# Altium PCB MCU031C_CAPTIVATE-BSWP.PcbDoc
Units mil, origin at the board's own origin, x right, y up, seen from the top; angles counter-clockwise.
Board outline 6000 x 3500 mil, 2 copper layers (Top Layer, Bottom Layer), stack 62 mil thick; 15 components, 47 nets, 54 pads, 27 vias.
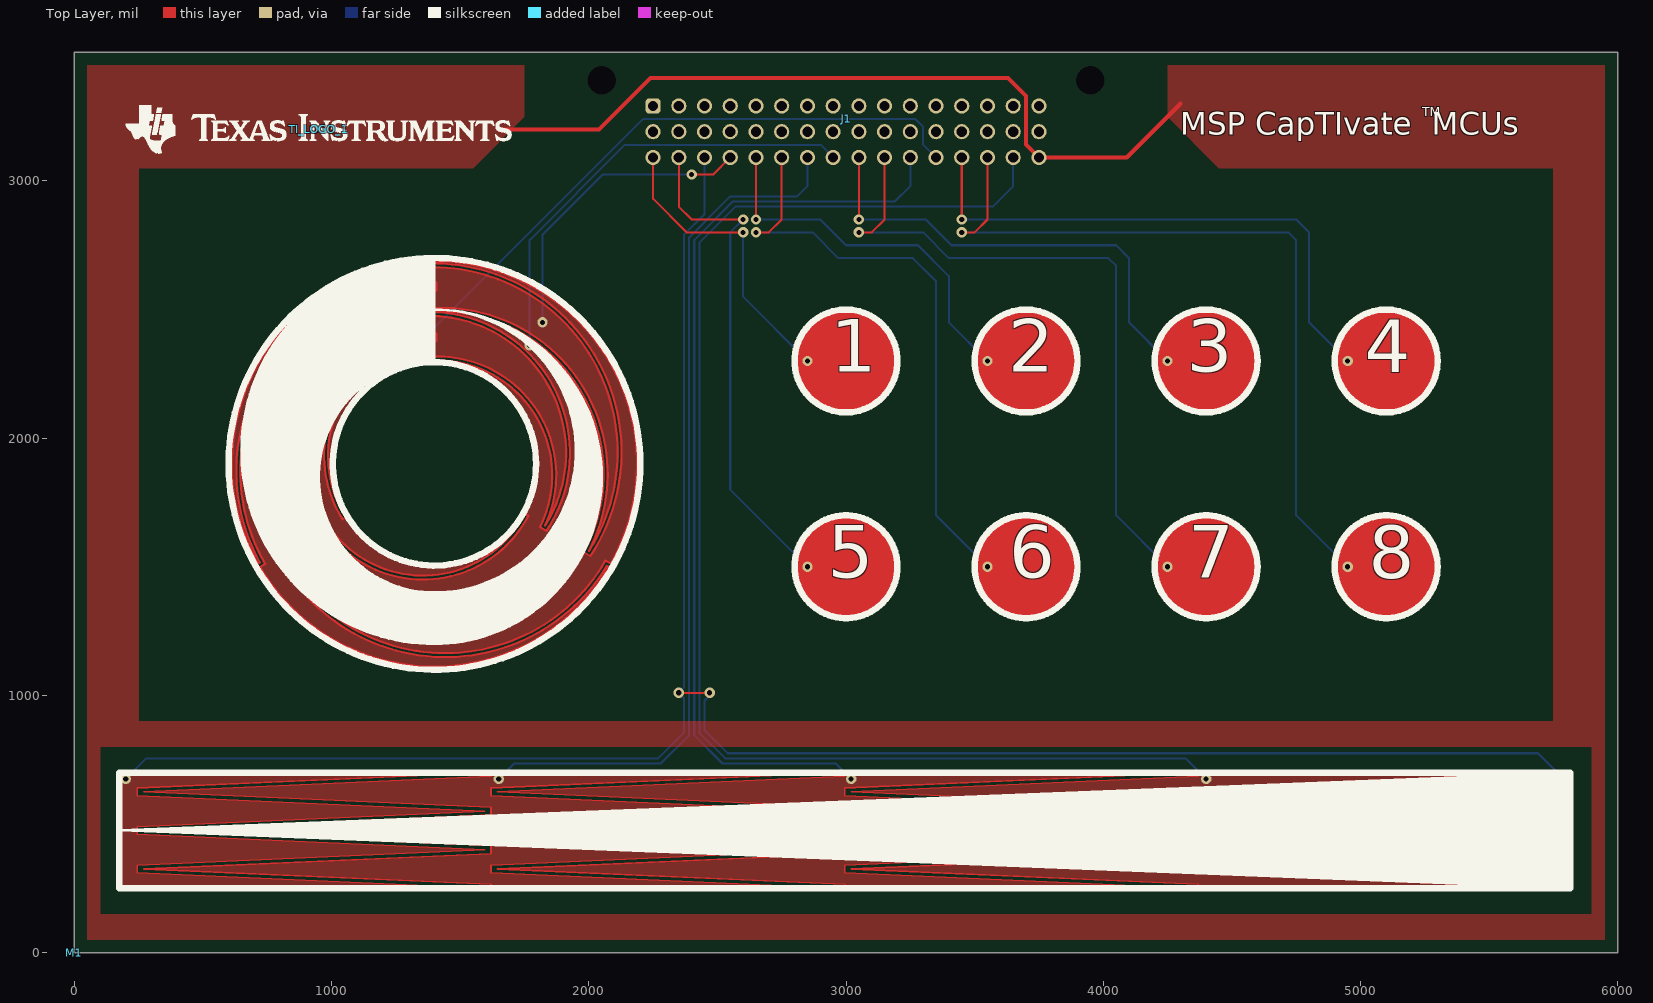
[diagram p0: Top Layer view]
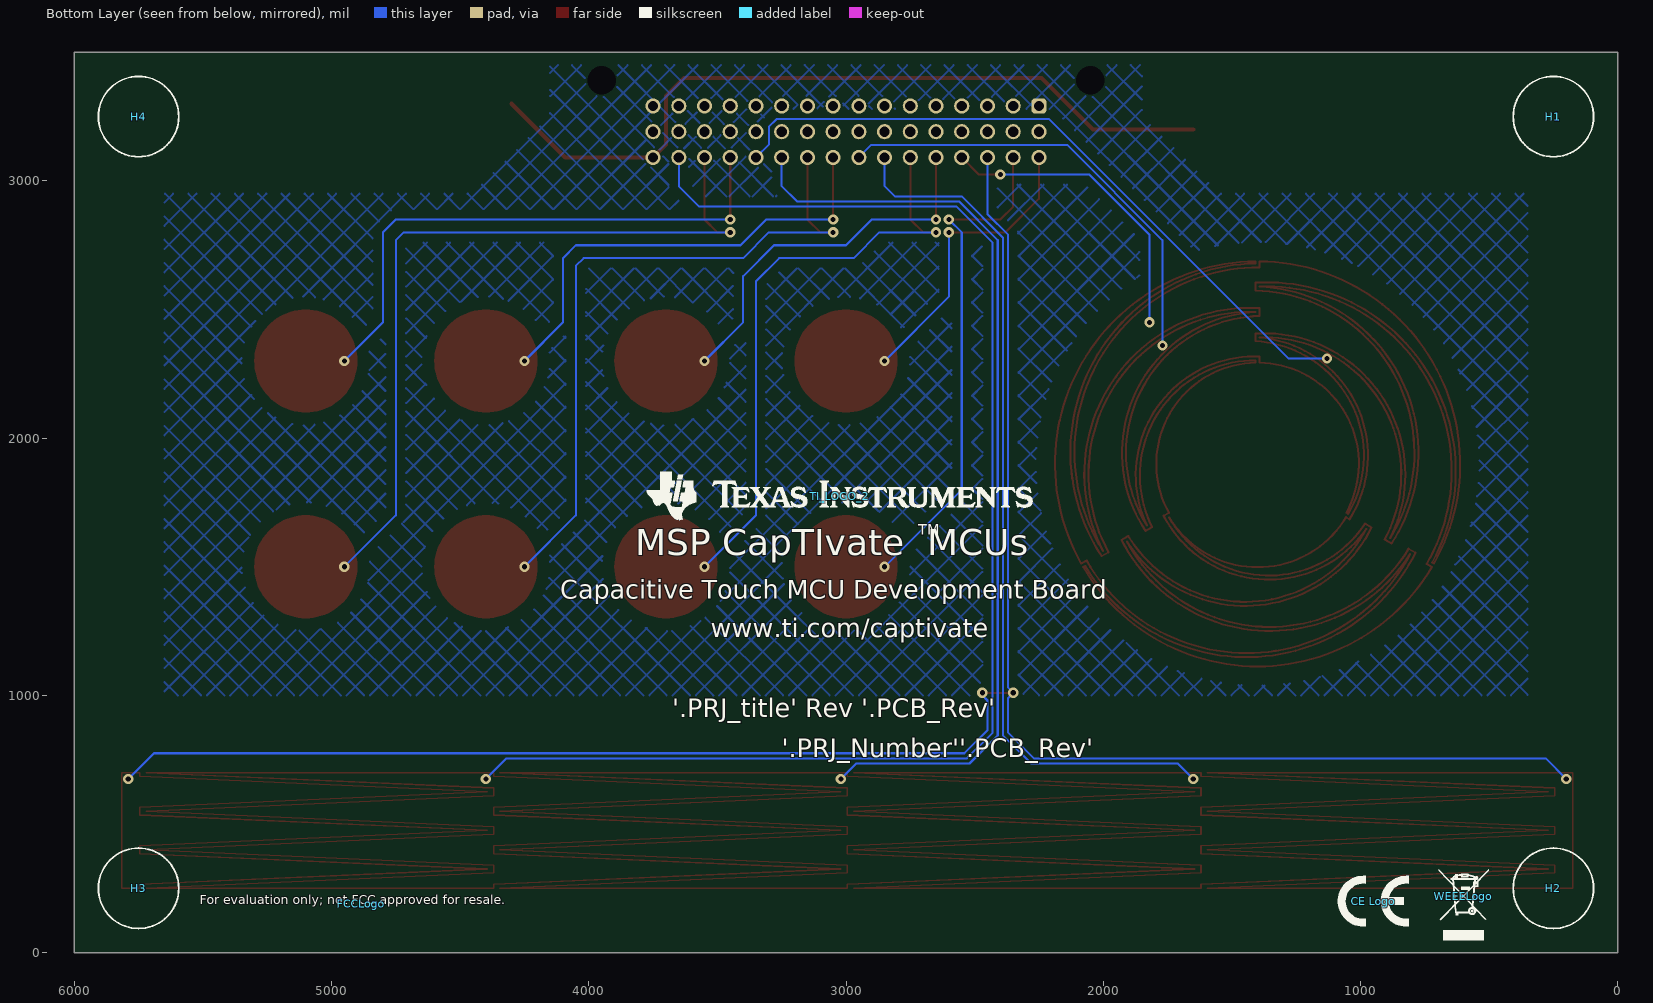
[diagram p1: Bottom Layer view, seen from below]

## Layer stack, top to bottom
Top Solder: solder mask 0.4, Solder Resist, Dk 3.5
Top Layer: signal copper 1.4
Dielectric1: core 59.2, FR-4, Dk 4.8
Bottom Layer: signal copper 1.4
Bottom Solder: solder mask 0.4, Solder Resist, Dk 3.5

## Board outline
0,0 0,3500 6000,3500 6000,0

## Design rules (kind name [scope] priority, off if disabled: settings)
AcuteAngle [All] p1: minimum=4.50000000000000E+0001 checktracksonly=FALSE
AssemblyTestPointUsage [All] p1: valid=2
Clearance Clearance_FiducialMark [IsKeepOut and InComponentClass('FiducialMark') vs IsPad and InComponentClass('FiducialMark')] p1: gap=0 ignorepadtopadclearanceinfootprint=FALSE
Clearance Clearance_Poly_Bottom_To_Track [OnBottom And InPolygon vs IsTrack] p2: gap=32 ignorepadtopadclearanceinfootprint=FALSE except(0: Arc-Hole Track-Hole SMDPad-Hole THPad-Hole Via-Hole Fill-Hole Poly-Hole Region-Hole Text-Hole)
Clearance Clearance_Poly_Connectors [(InNamedPolygon('Top Layer Pour')) OR (InNamedPolygon('Bottom Layer Pour')) vs (InComponent('J1')) OR (Incomponent('J2'))] p3: gap=40 ignorepadtopadclearanceinfootprint=FALSE except(0: Arc-Hole Track-Hole SMDPad-Hole THPad-Hole Via-Hole Fill-Hole Poly-Hole Region-Hole Text-Hole)
Clearance Clearance_Poly_Components [(InNamedPolygon('Top Layer Pour')) OR (InNamedPolygon('Bottom Layer Pour'))] p4: gap=20 ignorepadtopadclearanceinfootprint=FALSE except(0: Arc-Hole Track-Hole SMDPad-Hole THPad-Hole Via-Hole Fill-Hole Poly-Hole Region-Hole Text-Hole)
Clearance Clearance_General [All] p5: gap=6 ignorepadtopadclearanceinfootprint=FALSE except(0: Arc-Hole Track-Hole SMDPad-Hole THPad-Hole Via-Hole Fill-Hole Poly-Hole Region-Hole Text-Hole)
Clearance Clearance_BoardEdge_MountingHoles [OnCopper and InComponentClass('Mounting Holes') vs IsKeepOut] p6: gap=40 ignorepadtopadclearanceinfootprint=FALSE except(0: Arc-Hole Track-Hole SMDPad-Hole THPad-Hole Via-Hole Fill-Hole Poly-Hole Region-Hole Text-Hole)
Clearance Clearance_BoardEdge_Poly [OnCopper and InPoly vs IsKeepOut] p7: gap=7.87 ignorepadtopadclearanceinfootprint=FALSE except(0: Arc-Hole Track-Hole SMDPad-Hole THPad-Hole Via-Hole Fill-Hole Poly-Hole Region-Hole Text-Hole)
Clearance Clearance_BoardEdge [OnCopper and Not InComponentClass('Logo') and not InComponentClass('FiducialMark') and not InRegion(1000,500,4000,800) and Not IsKeepout vs IsKeepOut] p8: gap=7.87 ignorepadtopadclearanceinfootprint=FALSE except(0: Arc-Hole Track-Hole SMDPad-Hole THPad-Hole Via-Hole Fill-Hole Poly-Hole Region-Hole Text-Hole)
ComponentClearance ComponentClearance_Overlay [HasFootprint('MCH036')] p1: gap=0 collisioncheckmode=3 verticalgap=0 showdistances=FALSE
ComponentClearance ComponentClearance_Logo [InComponentClass('Logo')] p2: gap=7.87 collisioncheckmode=3 verticalgap=7.87 showdistances=TRUE
ComponentClearance ComponentClearance_ScrewToNut [(HasFootprint('NY PMS 440 0025 PH')) vs (HasFootprint('Keystone_1902C'))] p3: gap=5 collisioncheckmode=3 verticalgap=10 showdistances=FALSE
ComponentClearance ComponentClearance_MountingHoles [InComponentClass('Mounting Holes')] p4: gap=250 collisioncheckmode=3 verticalgap=100000 showdistances=FALSE
ComponentClearance ComponentClearance_SmallPassives [HasFootprint('0201*') or HasFootprint('0402*') or HasFootprint('0508') or HasFootprint('0603*') or HasFootprint('0612') or HasFootprint('0805*') or HasFootprint('0815*') or HasFootprint('0830*') or HasFootprint('1206*') or HasFootprint('1210*') or HasFootprint('1808*') or HasFootprint('1812*') or HasFootprint('1825*') or HasFootprint('2010*') or HasFootprint('2220*') or HasFootprint('2225*') or HasFootprint('2512*') or HasFootprint('2728*') or HasFootprint('3518*') vs HasFootprint('0201*') or HasFootprint('0402*') or HasFootprint('0508') or HasFootprint('0603*') or HasFootprint('0612') or HasFootprint('0805*') or HasFootprint('0815*') or HasFootprint('0830*') or HasFootprint('1206*') or HasFootprint('1210*') or HasFootprint('1808*') or HasFootprint('1812*') or HasFootprint('1825*') or HasFootprint('2010*') or HasFootprint('2220*') or HasFootprint('2225*') or HasFootprint('2512*') or HasFootprint('2728*') or HasFootprint('3518*')] p5: gap=20 collisioncheckmode=3 verticalgap=10 showdistances=FALSE
ComponentClearance ComponentClearance_THtoSMT [IsThruComponent vs IsSMTComponent] p6: gap=10 collisioncheckmode=3 verticalgap=100000 showdistances=TRUE
ComponentClearance ComponentClearance_THtoTH [IsThruComponent vs IsThruComponent] p7: gap=50 collisioncheckmode=3 verticalgap=100000 showdistances=FALSE
ComponentClearance [All] p8: gap=40 collisioncheckmode=3 verticalgap=10 showdistances=FALSE
DiffPairsRouting [All] p1: maxlimit=100 minlimit=10 mostfreqgap=10 toplayer_minwidth=15 toplayer_maxwidth=15 toplayer_prefwidth=15 bottomlayer_minwidth=15 bottomlayer_maxwidth=15 bottomlayer_prefwidth=15 maxuncoupledlength=1000
FabricationTestPointUsage TestPointUsage [All] p1: valid=2 allowmultiple=FALSE
FabricationTestpoint Testpoint [All] p1: side=3 testpointundercomponent=TRUE minsize=40 maxsize=100 preferedsize=60 minholesize=0 maxholesize=40 preferedholesize=32 testpointgrid=1 allowsidetop=TRUE allowsidebottom=TRUE usegrid=TRUE gridtolerance=0.01
FanoutControl Fanout_LCC [IsLCC] p1: bgadir=Out bgaviamode=Centered fanoutstyle=Auto fanoutdirection=Alternating viagrid=1 // Fanout_LCC (Default Rule)
FanoutControl Fanout_BGA [IsBGA] p2: bgadir=Out bgaviamode=Centered fanoutstyle=Auto fanoutdirection=Alternating viagrid=1 // Fanout_BGA (Default Rule)
FanoutControl Fanout_Default [All] p4: bgadir=Out bgaviamode=Centered fanoutstyle=Auto fanoutdirection=Alternating viagrid=1 // Fanout_Default (Default Rule)
FanoutControl Fanout_Small [(CompPinCount < 5)] p5: bgadir=Out bgaviamode=Centered fanoutstyle=Auto fanoutdirection=OutThenIn viagrid=1 // Fanout_Small (Default Rule)
HoleSize [All] p1: absolutevalues=TRUE maxlimit=251 minlimit=8 maxpercent=80.000 minpercent=20.000
MinimumAnnularRing [All] p1: minimumring=9
MinimumSolderMaskSliver MinimumSolderMaskSliver_Logo [InComponentClass('Logo') vs InComponentClass('Logo')] p1: minsoldermaskwidth=0.7
MinimumSolderMaskSliver [All] p2: minsoldermaskwidth=4
PlaneConnect [All] p1: planeconnectstyle=Relief reliefexpansion=10 reliefentries=4 reliefconductorwidth=10 reliefairgap=10
PolygonConnect [All] p1: connectstyle=Direct reliefconductorwidth=10 reliefentries=4 polygonreliefangle="45 Angle" airgapwidth=10
RoutingVias [All] p1: holewidth=16 width=34 viastyle="Through Hole" minholewidth=8 minwidth=26 maxholewidth=40 maxwidth=65
SilkToSilkClearance [All] p1: silktosilkclearance=5
SilkToSolderMaskClearance SilkscreenOverComponentPads [IsPad] p1: minsilkscreentomaskgap=5 clearancetoexposedcopper=TRUE
SolderMaskExpansion [All] p1: expansion=2
Width [All] p1: maxlimit=100 minlimit=6 preferedwidth=10 checkconnectedcopper=TRUE
16 further rules are at their usual default settings.

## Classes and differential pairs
component class Logo: TI_LOGO_1 TI_LOGO_2
component class AssemblyNote: ZZ1 ZZ2 ZZ3 ZZ4

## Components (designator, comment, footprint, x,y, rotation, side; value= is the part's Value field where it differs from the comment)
"CE Logo" "CE Mark" CE_Mark_5mm 950,200 r180 bottom
FCCLogo "FCC disclaimer" FCC_disclaimer 4885,190 r180 bottom
H1 "SJ61A1" Bumpon_SJ61A1 250,3250 r90 bottom
H2 "SJ61A1" Bumpon_SJ61A1 250,250 r90 bottom
H3 "SJ61A1" Bumpon_SJ61A1 5750,250 r90 bottom
H4 "SJ61A1" Bumpon_SJ61A1 5750,3250 r90 bottom
J1 "09231486921" Harting_09231486921 3000,3500 r0 top
M1 "MCH036A" MCH036 0,0 r0 top
TI_LOGO_1 "Texas Instruments" TI_Horizontal_Overlay_Medium 950,3200 r0 top
TI_LOGO_2 "Texas Instruments" TI_Horizontal_Overlay_Medium 3025,1775 r180 bottom
WEEELogo "WEEE logo" WEEE_Minimum 600,220 r180 bottom
ZZ1 "These assemblies are ESD sensitive, ESD precautions shall be observed." AssemblyNote 200,-300 r0 top
ZZ2 "These assemblies must be clean and free from flux and all contaminants. Use of no clean flux is not acceptable." AssemblyNote 200,-450 r0 top
ZZ3 "These assemblies must comply with workmanship standards IPC-A-610 Class 2, unless otherwise specified." AssemblyNote 200,-600 r0 top
ZZ4 "Overlay will be installed during final test" AssemblyNote 200,-740 r0 top

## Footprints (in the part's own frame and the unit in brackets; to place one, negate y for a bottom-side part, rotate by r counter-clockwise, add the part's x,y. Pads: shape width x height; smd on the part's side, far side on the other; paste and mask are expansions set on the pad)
AssemblyNote [mil] "Assembly Note"
Bumpon_SJ61A1 [mil] "3M Cylindrical Bumpon black"
  round 1 on Mech4: 0(0,0)
  silkscreen extent -156,-156 156,156, body extent -156,-155 156,156, height 201
CE_Mark_5mm [mil] "Minimum text height for CE Mark"
  silkscreen extent -138,-98 138,98
FCC_disclaimer [mil]
Harting_09231486921 [mm] "Header(shrouded), 2.54mm, 16x3, R/A, TH"
  rrect50% 1.5x1.5 hole 1: A1(-19.05,-5.3)
  round 1.5 hole 1: A2(-16.51,-5.3) A3(-13.97,-5.3) A4(-11.43,-5.3) A5(-8.89,-5.3) A6(-6.35,-5.3) A7(-3.81,-5.3) A8(-1.27,-5.3) A9(1.27,-5.3) A10(3.81,-5.3) A11(6.35,-5.3) A12(8.89,-5.3) A13(11.43,-5.3) A14(13.97,-5.3) A15(16.51,-5.3) A16(19.05,-5.3) B1(-19.05,-7.84) B2(-16.51,-7.84) B3(-13.97,-7.84) B4(-11.43,-7.84) B5(-8.89,-7.84) B6(-6.35,-7.84) B7(-3.81,-7.84) B8(-1.27,-7.84) B9(1.27,-7.84) B10(3.81,-7.84) B11(6.35,-7.84) B12(8.89,-7.84) B13(11.43,-7.84) B14(13.97,-7.84) B15(16.51,-7.84) B16(19.05,-7.84) C1(-19.05,-10.38) C2(-16.51,-10.38) C3(-13.97,-10.38) C4(-11.43,-10.38) C5(-8.89,-10.38) C6(-6.35,-10.38) C7(-3.81,-10.38) C8(-1.27,-10.38) C9(1.27,-10.38) C10(3.81,-10.38) C11(6.35,-10.38) C12(8.89,-10.38) C13(11.43,-10.38) C14(13.97,-10.38) C15(16.51,-10.38) C16(19.05,-10.38)
  round 2.5 hole 2.8 unplated mask+0.102: MH1(-24.13,-2.76) MH2(24.13,-2.76)
  body extent -27,-10.68 27,7.34, height 9.35
MCH036 [mil] "CAPTIVATE-BSWP Overlay"
  body extent 0,0 6000,3500, height 60
TI_Horizontal_Overlay_Medium [mil]
  silkscreen extent -750,-94 750,94
WEEE_Minimum [mil] "WEEElie bin"
  silkscreen extent -95,-172 99,104

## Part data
"CE Logo": library part CMP-0074844-1
FCCLogo: library part CMP-0074847-1, "FCC_disclaimer"
H1 H2 H3 H4: "Bumpon, Cylindrical, 0.312 X 0.200, Black", Manufacturer=3M, Supplier Part Number 1=SJ5746-0-ND
J1: library part CMP-0084037-1, "Header(shrouded), 2.54mm, 16x3, Gold, R/A, TH", Current_A=2A, Manufacturer=Harting
M1: library part MCH036, "CAPTIVATE-BSWP Overlay", Alternate Manufacturer=-
TI_LOGO_1 TI_LOGO_2: library part TI_Logo, "Texas Instrument Corporate Signature"
WEEELogo: library part CMP-0074769-1
ZZ1: library part CMP-0077236-1
ZZ2: library part CMP-0077237-1
ZZ3: library part CMP-0077238-1
ZZ4: library part CMP-0003615-1, "This Assembly Note will show in the PcbDoc and associated outputs"

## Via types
v1: diameter 40, hole 20, Top Layer to Bottom Layer, tented both sides, 27 vias

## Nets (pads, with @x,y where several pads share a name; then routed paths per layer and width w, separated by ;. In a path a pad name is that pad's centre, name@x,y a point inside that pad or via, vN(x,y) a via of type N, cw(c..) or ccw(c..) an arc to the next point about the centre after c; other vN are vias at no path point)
CAP0.0: J1.C1 | length 1168.7
  Top Layer w8: J1.C1 2250,2930 2380,2800 v1(2600,2800)
  Bottom Layer w8: v1(2600,2800) 2600,2550 v1(2850,2300)
CAP0.1: J1.C2 | length 1957
  Top Layer w8: J1.C2 2350,2900 2400,2850 v1(2600,2850)
  Bottom Layer w8: v1(2600,2850) 2550,2800 2550,1800 v1(2850,1500)
CAP0.2: J1.C3 | length 28498.6
  Top Layer w6: 175,250 175,700 1595,700 245,640 245,610 1595,550 245,490 245,460 1595,400 245,340 245,310 1595,250 175,250 ; 4395,325 5745,265 5745,250 5815,250 5815,700 5745,700 5745,685 4395,625 5745,565 5745,535 4395,475 5745,415 5745,385 4395,325
  Top Layer w8: v1(2350,1010) v1(2470,1010)
  Bottom Layer w8: v1(200,675) 280,755 2270,755 2370,855 2370,990 v1(2350,1010) 2370,1030 2370,2790 2450,2870 J1.C3 ; v1(2470,1010) 2470,1000 2450,980 2450,865 2540,775 5690,775 v1(5790,675)
CAP0.3: J1.C4 | length 13714
  Top Layer w7.87: 714.19,1513.14 cw(c1400,1900) 1392.13,2687.36 1392.13,2663.8 cw(c1393.9,1945.75) 2000.85,1562.06 ccw(c1427.26,1860.36) 1392.13,2505.93 1392.13,2475.05 cw(c1379.26,1942.96) 1830.13,1660.13 ccw(c1412.1,1855.9) 1392.13,2317.07 1392.13,2293.62 ccw(c1400,1900) 1055,1710.33 1048.11,1706.09 cw(c1432.66,1931.7) 1407.87,2376.87 1407.87,2406.59 ccw(c1373.66,1859.64) 884.93,1611.72 884.43,1611.34 cw(c1421.09,1942.8) 1407.87,2573.44 1407.87,2604.3 ccw(c1363.43,1871.84) 721.06,1517.11 714.19,1513.14
  Top Layer w8: v1(2400,3025) 2483.66,3025 J1.C4
  Bottom Layer w8: v1(1820,2450) 1820,2790 2055,3025 v1(2400,3025)
CAP1.0: J1.C5 | length 1474.6
  Top Layer w8: v1(2650,2850) J1.C5
  Bottom Layer w8: v1(2650,2850) 2900,2850 3000,2750 3280,2750 3400,2630 3400,2450 v1(3550,2300)
CAP1.1: J1.C6 | length 2333.6
  Top Layer w8: v1(2650,2800) 2700,2800 2750,2850 J1.C6
  Bottom Layer w8: v1(2650,2800) 2870,2800 2970,2700 3260,2700 3350,2610 3350,1700 v1(3550,1500)
CAP1.2: J1.C7 | length 22495.6
  Top Layer w6: 270,325 1620,265 1620,250 2970,250 1620,310 1620,340 2970,400 1620,460 1620,490 2970,550 1620,610 1620,640 2970,700 1620,700 1620,685 270,625 1620,565 1620,535 270,475 1620,415 1620,385 270,325
  Bottom Layer w8: v1(1650,675) 1710,735 2280,735 2390,845 2390,2780 2550,2940 2810,2940 2850,2980 J1.C7
CAP1.3: J1.C8 | length 14285.9
  Top Layer w5.91: 1979.28,1556.46 2006,1541.03
  Top Layer w7.87: 1979.28,1556.46 ccw(c1426.52,1860.33) 1407.87,2490.83 1407.87,2490.2 cw(c1379.26,1942.96) 1835.52,1639.46 1809.81,1654.46 ccw(c1412.1,1855.9) 1407.87,2301.7 1407.87,2293.62 cw(c1400,1900) 1744.67,1709.73 1765.13,1698.28 cw(c1355.76,1911.57) 977.2,1647.43 ccw(c1447.9,1895.84) 1902.45,1619 1928.69,1603.85 cw(c1352.38,1896.87) 807.53,1548.84 806.96,1548.52 ccw(c1442.67,1882.41) 2065.41,1524.92 2085.81,1513.14 ccw(c1400,1900) 1407.87,2687.36 1407.87,2679.42 cw(c1393.9,1945.75) 2006,1541.03
  Bottom Layer w8: v1(1770,2360) 1770,2770 2140,3140 2901.34,3140 J1.C8
CAP2.0: J1.C9 | length 1815.6
  Top Layer w8: v1(3050,2850) J1.C9
  Bottom Layer w8: v1(3050,2850) 3310,2850 3410,2750 4050,2750 4100,2700 4100,2450 v1(4250,2300)
CAP2.1: J1.C10 | length 2668.7
  Top Layer w8: v1(3050,2800) 3100,2800 3150,2850 J1.C10
  Bottom Layer w8: v1(3050,2800) 3300,2800 3400,2700 4020,2700 4050,2670 4050,1700 v1(4250,1500)
CAP2.2: J1.C11 | length 22739.7
  Top Layer w6: 1645,325 2995,385 2995,415 1645,475 2995,535 2995,565 1645,625 2995,685 2995,700 4345,700 2995,640 2995,610 4345,550 2995,490 2995,460 4345,400 2995,340 2995,310 4345,250 2995,250 2995,265 1645,325
  Bottom Layer w8: v1(3020,675) 2960,735 2520,735 2410,845 2410,2770 2560,2920 3190,2920 3250,2980 J1.C11
CAP2.3: J1.C12 | length 15226.2
  Top Layer w7.87: 1392.12,2588.68 ccw(c1421.1,1942.8) 879.18,1590.21 905.93,1605.66 cw(c1373.66,1859.64) 1392.43,2391.55 ccw(c1432.66,1931.7) 1042.75,1684.65 1055.97,1692.47 ccw(c1400,1900) 1743.88,1692.21 cw(c1355.76,1911.57) 982.43,1667.89 956.74,1652.83 ccw(c1447.9,1895.84) 1907.77,1597.83 cw(c1352.38,1896.86) 812.85,1570.1 786.12,1554.67 ccw(c1442.67,1882.41) 2071.06,1503.47 2077.94,1499.5 cw(c1400,1900) 722.06,1499.5 742.46,1511.28 cw(c1363.43,1871.84) 1392.13,2589.32 1392.13,2588.68
  Bottom Layer w8: v1(1130,2310) 1280,2310 2210,3240 3270,3240 3300,3210 3300,3141.34 J1.C12
CAP3.0: J1.C13 | length 2174.2
  Top Layer w8: v1(3450,2850) J1.C13
  Bottom Layer w8: v1(3450,2850) 4750,2850 4800,2800 4800,2450 v1(4950,2300)
CAP3.1: J1.C14 | length 3027.3
  Top Layer w8: v1(3450,2800) 3500,2800 3550,2850 J1.C14
  Bottom Layer w8: v1(3450,2800) 4720,2800 4750,2770 4750,1700 v1(4950,1500)
CAP3.2: J1.C15 | length 24468
  Top Layer w6: 3020,325 4370,385 4370,415 3020,475 4370,535 4370,565 3020,625 4370,685 4370,700 5720,700 4370,640 4370,610 5720,550 4370,490 4370,460 5720,400 4370,340 4370,310 5720,250 4370,250 4370,265 3020,325
  Bottom Layer w8: J1.C15 3650,2980 3570,2900 2570,2900 2430,2760 2430,855 2530,755 4320,755 v1(4400,675)
CAP3.3: J1.C16 | length 3057.6
  Top Layer w16: 1650,3200 2040,3200 2240,3400 3630,3400 3700,3330 3700,3141.34 J1.C16 4091.34,3091.34 4300,3300
GND: J1.A1 J1.A16
NetJ1_A2: J1.A2
NetJ1_A3: J1.A3
NetJ1_A4: J1.A4
NetJ1_A5: J1.A5
NetJ1_A6: J1.A6
NetJ1_A7: J1.A7
NetJ1_A8: J1.A8
NetJ1_A9: J1.A9
NetJ1_A10: J1.A10
NetJ1_A11: J1.A11
NetJ1_A12: J1.A12
NetJ1_A13: J1.A13
NetJ1_A14: J1.A14
NetJ1_A15: J1.A15
NetJ1_B1: J1.B1
NetJ1_B2: J1.B2
NetJ1_B3: J1.B3
NetJ1_B4: J1.B4
NetJ1_B5: J1.B5
NetJ1_B6: J1.B6
NetJ1_B7: J1.B7
NetJ1_B8: J1.B8
NetJ1_B9: J1.B9
NetJ1_B10: J1.B10
NetJ1_B11: J1.B11
NetJ1_B12: J1.B12
NetJ1_B13: J1.B13
NetJ1_B14: J1.B14
NetJ1_B15: J1.B15
NetJ1_B16: J1.B16
pads on no net: H1.0 H2.0 H3.0 H4.0 J1.MH1 J1.MH2

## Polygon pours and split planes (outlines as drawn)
CAP3.3 on Top Layer "Top Layer-No Net 4" (solid, remove dead copper, pour order 21): 50,800 5950,800 5950,950 5750,950 5750,900 250,900 250,950 50,950 50,800
CAP3.3 on Top Layer "Top Layer-No Net 3" (solid, remove dead copper, pour order 16): 1750,3450 50,3450 50,50 5950,50 5950,3450 4250,3450 4250,3250 4450,3050 5750,3050 5750,950 5900,800 5900,300 5900,150 5250,150 100,150 100,800 250,950 250,1850 250,3050 800,3050 1550,3050 1750,3250 1750,3450
CAP1.3 on Top Layer "Top" (solid, remove dead copper, pour order 14): 803.47,1546.68 cw(c806.96,1548.52) 804.99,1551.94 805.55,1552.26 cw(c807.53,1548.84) 810.86,1550.97 ccw(c1352.38,1896.87) 1923.46,1602.31 1903.81,1613.65 cw(c1447.9,1895.84) 973.71,1645.59 cw(c977.2,1647.43) 977.2,1651.38 cw(c977.2,1647.43) 980.45,1649.69 ccw(c1355.76,1911.57) 1759.84,1696.72 1742.74,1706.28 cw(c1744.67,1709.73) 1741.22,1711.67 ccw(c1400,1900) 1789.75,1900 ccw(c1400,1900) 1407.82,2289.67 ccw(c1400.84,1900.94) 1407.79,2289.67 1407.82,2289.67 cw(c1407.87,2293.62) 1403.92,2293.62 1403.92,2301.7 cw(c1407.87,2301.7) 1407.84,2305.65 cw(c1412.1,1855.9) 1861.87,1855.9 cw(c1412.1,1855.9) 1815.01,1656.01 1834.28,1644.76 ccw(c1379.26,1942.96) 1923.29,1942.96 ccw(c1379.26,1942.96) 1407.7,2486.25 cw(c1407.87,2490.2) 1403.92,2490.2 1403.92,2490.83 cw(c1407.87,2490.83) 1407.76,2494.78 cw(c1426.52,1860.33) 2061.25,1860.33 cw(c1426.52,1860.33) 1984.59,1557.95 2004.75,1546.32 ccw(c1393.9,1945.75) 2123.75,1945.75 ccw(c1393.9,1945.75) 1407.83,2675.47 ccw(c1392.18,1945.8) 1407.8,2675.47 1407.83,2675.47 cw(c1407.87,2679.42) 1403.92,2679.42 1403.92,2687.36 cw(c1407.87,2687.36) 1407.91,2691.31 cw(c1400,1900) 2191.35,1900 cw(c1400,1900) 2089.26,1511.2 cw(c2085.81,1513.14) 2085.81,1509.19 cw(c2085.81,1513.14) 2083.84,1509.71 2066.86,1519.52 cw(c1442.67,1882.41)
CAP0.3 on Top Layer "Top" (solid, remove dead copper, pour order 12): 710.74,1511.2 ccw(c714.19,1513.14) 716.18,1509.72 723.03,1513.68 ccw(c721.06,1517.11) 725.02,1517.11 ccw(c721.06,1517.11) 724.52,1519.02 cw(c1363.43,1871.84) 1403.92,2600.57 1403.92,2577.3 ccw(c1421.09,1942.8) 881.07,1609.27 ccw(c884.43,1611.34) 886.78,1608.17 887.28,1608.54 ccw(c884.93,1611.72) 888.88,1611.72 ccw(c884.93,1611.72) 888.44,1613.53 cw(c1373.66,1859.64) 1403.92,2402.86 1403.92,2380.59 ccw(c1432.66,1931.7) 1044.7,1704.09 ccw(c1048.11,1706.09) 1050.21,1702.74 1057.05,1706.96 ccw(c1055,1710.33) 1058.95,1710.33 ccw(c1055,1710.33) 1058.45,1712.26 ccw(c1399.71,1898.89) 1058.46,1712.24 1058.45,1712.26 cw(c1400,1900) 1392.18,2289.67 ccw(c1392.13,2293.62) 1396.08,2293.62 1396.08,2313.27 cw(c1412.1,1855.9) 1869.75,1855.9 cw(c1412.1,1855.9) 1826.56,1661.83 ccw(c1830.13,1660.13) 1826.18,1660.13 ccw(c1830.13,1660.13) 1833.48,1658.03 ccw(c1379.26,1942.96) 1915.45,1942.96 ccw(c1379.26,1942.96) 1396.08,2478.89 1396.08,2502.18 cw(c1427.26,1860.36) 2069.83,1860.36 cw(c1427.26,1860.36) 1997.34,1563.88 ccw(c2000.85,1562.06) 2000.85,1558.1 ccw(c2000.85,1562.06) 2004.19,1559.94 ccw(c1393.9,1945.75) 2115.91,1945.75 ccw(c1393.9,1945.75) 1396.08,2667.75 1396.08,2687.36 ccw(c1392.13,2687.36) 1392.13,2691.31 ccw(c1392.13,2687.37) 1392.09,2691.31 ccw(c1400,1900)
CAP0.2 on Top Layer "Top Layer-CAPT_D.2" (solid, remove dead copper, pour order 15): 4395,475 5745,415 5745,385 4395,325 5745,265 5745,250 5815,250 5815,700 5745,700 5745,685 4395,625 5745,565 5745,535
CAP0.2 on Top Layer "Top Layer-CAPT_A.2" (solid, remove dead copper, pour order 17): 175,250 175,700 1595,700 245,640 245,610 1595,550 245,490 245,460 1595,400 245,340 245,310 1595,250
CAP1.2 on Top Layer "Top Layer-No Net" (solid, remove dead copper, pour order 18): 270,475 1620,415 1620,385 270,325 1620,265 1620,250 2970,250 1620,310 1620,340 2970,400 1620,460 1620,490 2970,550 1620,610 1620,640 2970,700 1620,700 1620,685 270,625 1620,565 1620,535
CAP2.2 on Top Layer "Top Layer-No Net 1" (solid, remove dead copper, pour order 19): 1645,325 2995,385 2995,415 1645,475 2995,535 2995,565 1645,625 2995,685 2995,700 4345,700 2995,640 2995,610 4345,550 2995,490 2995,460 4345,400 2995,340 2995,310 4345,250 2995,250 2995,265
CAP3.2 on Top Layer "Top Layer-No Net 2" (solid, remove dead copper, pour order 20): 3020,325 4370,385 4370,415 3020,475 4370,535 4370,565 3020,625 4370,685 4370,700 5720,700 4370,640 4370,610 5720,550 4370,490 4370,460 5720,400 4370,340 4370,310 5720,250 4370,250 4370,265
CAP2.3 on Top Layer "Top" (solid, remove dead copper, pour order 13): 718.66,1497.49 cw(c722.06,1499.5) 720.1,1502.93 737.07,1512.73 cw(c1363.43,1871.84) 1392.28,2593.27 cw(c1392.13,2589.32) 1396.08,2589.32 1396.08,2588.68 cw(c1392.13,2588.68) 1392.3,2584.73 ccw(c1421.1,1942.8) 880.46,1595.51 900.63,1607.16 cw(c1373.66,1859.64) 1392.57,2395.5 cw(c1392.43,2391.55) 1396.39,2391.55 cw(c1392.43,2391.55) 1392.78,2387.61 ccw(c1432.66,1931.7) 1044.05,1690.01 1053.95,1695.86 cw(c1055.96,1692.47) 1053.96,1695.87 cw(c1055.97,1692.47) 1059.37,1694.48 cw(c1400.01,1900.31) 1059.35,1694.51 1059.37,1694.48 ccw(c1400,1900) 1740.5,1694.26 ccw(c1743.88,1692.21) 1740.44,1694.16 1740.5,1694.26 cw(c1743.88,1692.21) 1747.83,1692.21 cw(c1743.88,1692.21) 1747.26,1690.17 1747.32,1690.27 cw(c1355.76,1911.57) 981.19,1662.58 961.93,1651.29 ccw(c1447.9,1895.84) 1904.44,1599.96 cw(c1907.77,1597.83) 1907.77,1601.78 cw(c1907.77,1597.83) 1911.72,1597.83 cw(c1907.77,1597.83) 1911.25,1595.96 cw(c1352.38,1896.86) 811.48,1564.75 791.33,1553.11 ccw(c1442.67,1882.41) 2067.68,1505.51 cw(c2071.06,1503.47) 2071.06,1507.42 cw(c2071.06,1503.47) 2073.04,1506.89 2079.91,1502.92 cw(c2077.94,1499.5) 2081.89,1499.5 cw(c2077.94,1499.5) 2081.34,1497.49 cw(c1400,1900)
GND on Bottom Layer "Bottom Layer-No Net" (hatched 45Degree grid 64 track 8, remove dead copper, pour order 22): 350,1000 5650,1000 5650,2950 4450,2950 4150,3250 4150,3450 1850,3450 1850,3300 1850,3250 1550,2950 350,2950 350,1000

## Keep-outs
Keep-Out Layer:
  text ".Layer_Name" at 67,-2318.49 h60

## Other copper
Top Layer:
  region net CAP0.0: 3000,2100 cw(c3000,2300) 2800,2300 cw(c3000,2300) 3000,2500 cw(c3000,2300) 3200,2300 cw(c3000,2300)
  region net CAP1.0: 3700,2100 cw(c3700,2300) 3500,2300 cw(c3700,2300) 3700,2500 cw(c3700,2300) 3900,2300 cw(c3700,2300)
  region net CAP2.0: 4200,2300 ccw(c4400,2300) 4400,2100 ccw(c4400,2300) 4600,2300 ccw(c4400,2300) 4400,2500 ccw(c4400,2300)
  region net CAP3.0: 4900,2300 ccw(c5100,2300) 5100,2100 ccw(c5100,2300) 5300,2300 ccw(c5100,2300) 5100,2500 ccw(c5100,2300)
  region net CAP0.1: 3000,1300 cw(c3000,1500) 2800,1500 cw(c3000,1500) 3000,1700 cw(c3000,1500) 3200,1500 cw(c3000,1500)
  region net CAP1.1: 3500,1500 ccw(c3700,1500) 3700,1300 ccw(c3700,1500) 3900,1500 ccw(c3700,1500) 3700,1700 ccw(c3700,1500)
  region net CAP2.1: 4200,1500 ccw(c4400,1500) 4400,1300 ccw(c4400,1500) 4600,1500 ccw(c4400,1500) 4400,1700 ccw(c4400,1500)
  region net CAP3.1: 4900,1500 ccw(c5100,1500) 5100,1300 ccw(c5100,1500) 5300,1500 ccw(c5100,1500) 5100,1700 ccw(c5100,1500)
  text ".Layer_Name" at 67,-2318.49 h60
Bottom Layer:
  pour cut-out: 1400,1037.5 cw(c1400,1900) 537.5,1900 cw(c1400,1900) 1400,2762.5 cw(c1400,1900) 2262.5,1900 cw(c1400,1900)
  pour cut-out: 3000,2050 cw(c3000,2300) 2750,2300 cw(c3000,2300) 3000,2550 cw(c3000,2300) 3250,2300 cw(c3000,2300)
  pour cut-out: 3700,2050 cw(c3700,2300) 3450,2300 cw(c3700,2300) 3700,2550 cw(c3700,2300) 3950,2300 cw(c3700,2300)
  pour cut-out: 4150,2300 ccw(c4400,2300) 4400,2050 ccw(c4400,2300) 4650,2300 ccw(c4400,2300) 4400,2550 ccw(c4400,2300)
  pour cut-out: 4850,2300 ccw(c5100,2300) 5100,2050 ccw(c5100,2300) 5350,2300 ccw(c5100,2300) 5100,2550 ccw(c5100,2300)
  pour cut-out: 3000,1250 cw(c3000,1500) 2750,1500 cw(c3000,1500) 3000,1750 cw(c3000,1500) 3250,1500 cw(c3000,1500)
  pour cut-out: 3450,1500 ccw(c3700,1500) 3700,1250 ccw(c3700,1500) 3950,1500 ccw(c3700,1500) 3700,1750 ccw(c3700,1500)
  pour cut-out: 4150,1500 ccw(c4400,1500) 4400,1250 ccw(c4400,1500) 4650,1500 ccw(c4400,1500) 4400,1750 ccw(c4400,1500)
  pour cut-out: 4850,1500 ccw(c5100,1500) 5100,1250 ccw(c5100,1500) 5350,1500 ccw(c5100,1500) 5100,1750 ccw(c5100,1500)
  text ".Layer_Name" at 67,-2318.49 h60

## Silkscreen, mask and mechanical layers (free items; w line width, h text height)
Top Overlay:
  circle w25: c1400,1900 r800.39
  circle w25: c5100,1500 r200
  circle w25: c4400,1500 r200
  circle w25: c3700,1500 r200
  circle w25: c3000,1500 r200
  circle w25: c5100,2300 r200
  circle w25: c4400,2300 r200
  circle w25: c3700,2300 r200
  circle w25: c1400,1900 r395.28
  circle w25: c3000,2300 r200
  region: 175,475 5815,700 5815,250
  region: 1400,1200 cw(c1400,1950) 1400,2700 1400,2300 ccw(c1400,1850) 1400,1400 ccw(c1400,1950) 1400,2500 cw(c1400,1850)
  lines w10: 5815,250 175,475 5815,700 ; 1400,1200 cw(c1400,1950) 1400,2700 1400,2300 ccw(c1400,1850) 1400,1400 ccw(c1400,1950) 1400,2500 cw(c1400,1850) 1400,1200
  lines w25: 175,250 175,700 5815,700 5815,250 175,250
  text "TM" at 5240,3240 h60
  text "MSP CapTIvate  MCUs" at 4300,3150 h150
  text "1" at 2940,2190 h350
  text "2" at 3630,2190 h350
  text "3" at 4325,2190 h350
  text "4" at 5017.5,2187.71 h350
  text "5" at 2930,1390 h350
  text "6" at 3635,1390 h350
  text "7" at 4330,1390 h350
  text "8" at 5032.5,1387.71 h350
  text ".Layer_Name" at 67,-2318.49 h60
Bottom Overlay:
  text "TM" at 2720,1610 h70
  text "MSP CapTIvate  MCUs" at 3820,1510 h175
  text "Capacitive Touch MCU Development Board" at 4110,1350 h125
  text "www.ti.com/captivate" at 3525,1200 h125
  text "'.PRJ_title' Rev '.PCB_Rev'" at 3675,890 h125
  text "'.PRJ_Number''.PCB_Rev'" at 3250,735 h125
  text ".Layer_Name" at 67,-2318.49 h60
Top Paste:
  text ".Layer_Name" at 67,-2318.49 h60
Bottom Paste:
  text ".Layer_Name" at 67,-2318.49 h60
Top Solder:
  text ".Layer_Name" at 67,-2318.49 h60
  text ".Layer_Name" at 67,-2318.49 h60
Bottom Solder:
  text ".Layer_Name" at 67,-2318.49 h60
Drill Guide:
  text ".Layer_Name" at 67,-2318.49 h60
M1 Board Outline:
  the board outline again, w10
  text ".Layer_Name" at 67,-2318.49 h60
M2 Board Dimensions:
  rectangle: -385.5,-1870.5 -10.5,-1745.5
  rectangle: -510.5,-1745.5 -385.5,-1620.5
  lines w7: -510.5,-1745.5 489.5,-1745.5 ; -385.5,-1870.5 -385.5,-1620.5 ; -260.5,-1870.5 -260.5,-1620.5 ; -10.5,-1870.5 -10.5,-1620.5 ; 239.5,-1870.5 239.5,-1620.5 ; -510.5,-1870.5 -510.5,-1620.5 489.5,-1620.5 489.5,-1870.5 -510.5,-1870.5
  lines w10: -510.5,-1935.5 -510.5,-1915.5 ; -450.5,-1945.5 -510.5,-1925.5 ; -450.5,-1905.5 -510.5,-1925.5 ; -286.42,-1925.5 -510.5,-1925.5 ; 265.42,-1925.5 489.5,-1925.5 ; 429.5,-1945.5 489.5,-1925.5 ; 429.5,-1905.5 489.5,-1925.5 ; 489.5,-1935.5 489.5,-1915.5
  text "1000 (mil)" at -276.42,-1961.49 h60
  text ".Layer_Name" at 67,-2318.49 h60
M3 3D STEP Top:
  text ".Layer_Name" at 67,-2318.49 h60
  text ".Layer_Name" at 67,-2318.49 h60
M4 3D STEP Bottom:
  text ".Layer_Name" at 67,-2318.49 h60
  text ".Layer_Name" at 67,-2318.49 h60
M5 Assembly Top:
  lines w10: -802,-2390.17 5798,-2390.17 ; -802,-2186.83 5800,-2186.83 ; -802,-1983.5 -802,-2593.5 3203,-2593.5 5800,-2593.5 5800,-1983.5 -801.5,-1983.5 -801.5,-2593.5 774,-2593.5 ; 1663,-2593.5 1663,-1983.5 ; 2930,-2186.83 2930,-1983.5 ; 3770,-2186.83 3770,-1983.5 ; 4392,-2600 4392,-2397.17
  text "COMPONENTS MARKED 'DNP' SHOULD NOT BE POPULATED." at 643.5,-1778.5 h60
  text "ASSEMBLY VARIANT:" at 643,-1894 h60
  text ".VariantName" at 1679,-1894 h60
  text "PCB VIEWED FROM TOP SIDE" at -738.5,-2115.67 h60
  text "BOARD #:" at 1738,-2115.67 h60
  text ".PRJ_Number" at 2283.5,-2115.67 h60
  text "REV:" at 3128,-2115.67 h60
  text ".PCB_Rev" at 3419.5,-2115.67 h60
  text "SVN REV:" at 3966,-2115.67 h60
  text ".VersionControl_RevNumber" at 4472,-2115.67 h60
  text "PLOT NAME =" at -738.5,-2524.34 h60
  text ".plot_File_Name" at 67,-2524.34 h60
  text "GENERATED    :" at 1740,-2524.34 h60
  text ".Print_Date" at 2609.5,-2524.34 h60
  text ".Print_Time" at 3338.5,-2524.34 h60
  text "TEXAS INSTRUMENTS" at 4603,-2524.34 h60
M6 Assembly Bottom:
  lines w10: -802.5,-2187.33 5799.5,-2187.33 ; -800.5,-2390.67 5799.5,-2390.67 ; 605.5,-2600.5 605.5,-2397.67 ; 1227.5,-2187.33 1227.5,-1984 ; 2067.5,-2187.33 2067.5,-1984 ; 3334.5,-2594 3334.5,-1984 ; 4223.5,-2594 5799,-2594 5799,-1984 -802.5,-1984 -802.5,-2594 1794.5,-2594 5799.5,-2594 5799.5,-1984
  text "COMPONENTS MARKED 'DNP' SHOULD NOT BE POPULATED." at 5592,-1778 h60
  text ".VariantName" at 4548,-1894 h60
  text "ASSEMBLY VARIANT:" at 5587,-1894 h60
  text ".PCB_Rev" at 1860,-2110 h60
  text ".PRJ_Number" at 2714,-2116.17 h60
  text "BOARD #:" at 3259.5,-2116.17 h60
  text "PCB VIEWED FROM BOTTOM SIDE" at 5736,-2116.17 h60
  text "IGNORE ->" at 2037.85,-2318.49 h60
  text "TEXAS INSTRUMENTS" at 394.5,-2524.84 h60
  text ".plot_File_Name" at 4930.5,-2524.84 h60
  text "PLOT NAME =" at 5736,-2524.84 h60
  text ".Print_Time" at 1690,-2530 h60
  text ".Print_Date" at 2419,-2530 h60
  text "GENERATED    :" at 3288.5,-2530 h60
M7 LPKF Text Top:
  circle w10: c5100,1500 r250
  circle w10: c4400,1500 r250
  circle w10: c3700,1500 r250
  circle w10: c3000,1500 r250
  circle w10: c5100,2300 r250
  circle w10: c4400,2300 r250
  circle w10: c3700,2300 r250
  circle w10: c3000,2300 r250
M9 Title Sheet:
  drawing of 57 lines, arcs and shapes, not listed
  text "1" at 229.84,6576.5 h70
  text "2" at 2725.5,6576.5 h70
  text "3" at 5214.84,6576.5 h70
  text "4" at 7721.51,6576.5 h70
  text "5" at 10220.5,6576.5 h70
  text "6" at 12725.5,6576.5 h70
  text "A" at -926.5,5433.5 h70
  text "A" at 13873.5,5433.5 h70
  text "B" at -926.5,3053.5 h70
  text "B" at 13873.5,3053.5 h70
  text "C" at -926.5,678.5 h70
  text "C" at 13873.5,678.5 h70
  text "PROJECT TITLE:" at 10833.5,-1182.5 h45
  text "TICAPEVM_BSWPDEMO" at 10883.5,-1315.83 h70
  text "DESIGNED FOR:" at 10833.5,-1483.5 h45
  text ".PRJ_Customer" at 10883.5,-1623.5 h70
  text "D" at -926.5,-1691.5 h70
  text "D" at 13873.5,-1691.5 h70
  text "FILE NAME:" at 10833.5,-1783.5 h45
  text ".PCB_File_Name_No_Path" at 10883.5,-1903.5 h70
  text "Texas Instruments (TI) and/or its licensors do not warrant the accuracy or completeness of this specification" at 5864,-2065.34 h45
  text "ENGINEER:" at 10833.5,-2073.5 h45
  text "LAYOUT BY:" at 12338.5,-2073.5 h45
  text "or any information contained therein. TI and/or its licensors do not warrant that this design will meet" at 5819.01,-2178 h45
  text "W. Schnoor" at 10883.5,-2228.49 h70
  text "W. Schnoor" at 12389,-2228.49 h70
  text "the specifications, will be suitable for your application or fit for any particular purpose, or will operate in" at 5819.01,-2290.67 h45
  text ".Layer_Name" at 67,-2318.49 h60
  text "ALTIUM DESIGNER VERSION:" at 12338.5,-2383.5 h45
  text "an implementation. TI and/or its licensors do not warrant that the design is production worthy. You should" at 5819.01,-2403.33 h45
  text "completely validate and test your design implementation to confirm the system functionality for your application." at 5864,-2516 h45
  text ".print_Scale" at 10883.5,-2516.83 h70
  text ".Application_BuildNumber" at 12389,-2516.83 h70
  text "1" at 229.84,-2723.5 h70
  text "2" at 2725.5,-2723.5 h70
  text "3" at 5214.84,-2723.5 h70
  text "4" at 7721.51,-2723.5 h70
  text "5" at 10220.5,-2723.5 h70
  text "6" at 12725.5,-2723.5 h70
M10 Fab Notes:
  drawing of 207 lines, arcs and shapes, not listed
  text "DESIGN INFORMATION" at 11871.02,5350 h60
  text "(REFER ALSO ARRAY/PANEL PROFILING INFORMATION)" at 11509.46,5188.29 h60
  text "BOARD SIZE" at 10823.46,5184 h60
  text "6000 MIL" at 11285.78,5056.18 h60
  text "X" at 11791.46,5056.18 h60
  text "3500 MIL" at 12022.78,5056.18 h60
  text "Number of Layers :" at 11226.46,4859 h60
  text "2" at 12321.27,4849 h60
  text "MIN. TRACK WIDTH:" at 11226.46,4720 h60
  text "6" at 12322.7,4720 h60
  text "MIL" at 12477.46,4720 h60
  text "MIN. CLEARANCE:" at 11226.46,4588 h60
  text "6" at 12322.7,4588 h60
  text "MIL" at 12477.46,4588 h60
  text "MIN. VIA PAD SIZE:" at 11226.46,4456 h60
  text "40" at 12292.71,4456 h60
  text "MIL" at 12477.46,4456 h60
  text "0.05mm (2MIL)" at 11921.46,4314.29 h60
  text "MINIMUM ANNULAR RING" at 10897.23,4310 h60
  text "EXTERNAL" at 12629.46,4310 h60
  text "PER" at 11097.23,4192 h60
  text "IPC-D-275 CLASS 2 LEVEL C" at 11317.23,4192 h60
  text "MIL, HOLES" at 12805.46,4079.71 h60
  text "+/-" at 12413,4079 h60
  text "+/-" at 13267,4079 h60
  text "REGISTRATION TOLERANCES:" at 10897.23,4074 h60
  text "METAL" at 12097,4074 h60
  text "5" at 12673.2,4074 h60
  text "3" at 13506.2,4074 h60
  text "MIL" at 13622.46,4074 h60
  text "MATERIAL:" at 10822.46,3864.54 h60
  text "FR-4 High Tg" at 11808.9,3724.21 h60
  text "FR-4" at 11283.46,3715.64 h60
  text "X" at 11655.46,3715.64 h60
  text "OTHER" at 12731.46,3715.64 h60
  text "62 MIL (1.6mm) +/-10%" at 11563.56,3552.92 h60
  text "THICKNESS:" at 10897.23,3548.64 h60
  text "X" at 11435.4,3548.64 h60
  text "OTHER" at 12848.46,3548.64 h60
  text "TOLERANCE:" at 10897.23,3390.64 h60
  text "X" at 11736.53,3390.64 h60
  text "ANSI IPC-6012 TYPE 3 CLASS 2" at 11923.48,3390.64 h60
  text "OTHER +/-" at 11923.46,3234.64 h60
  text "BOW & TWIST:" at 10897.23,3077.64 h60
  text "X" at 11736.53,3077.64 h60
  text "ANSI IPC-6012 TYPE 3 CLASS 2" at 11923.48,3077.64 h60
  text "OTHER +/-" at 11923.46,2919.13 h60
  text "COPPER THICKNESS (FINISHED):" at 10822.46,2783.64 h60
  text "1.4MIL (1oz)" at 11702.46,2630.92 h60
  text "2MIL (1.4oz)" at 12469.46,2630.92 h60
  text "2.8MIL (2oz)" at 13196.46,2630.92 h60
  text "OUTER:" at 11179.46,2626.64 h60
  text "X" at 11574,2626 h60
  text "1.4MIL (1oz)" at 11702.46,2473.92 h60
  text "2.8MIL (2oz)" at 12469.46,2473.92 h60
  text "N/A" at 13196,2474.29 h60
  text "INNER SIGNAL:" at 10890.38,2469.64 h60
  text "X" at 11575.42,2469.64 h60
  text "DRILLING:" at 10822.46,2330.64 h60
  text "REFERENCE:" at 10897.23,2213.64 h60
  text "X" at 11545.46,2213.64 h60
  text "AS SHOWN" at 11732.46,2213.64 h60
  text "X" at 12446.46,2213.64 h60
  text "NC_DRILL FILES" at 12583.46,2213.64 h60
  text "PTH MIN COPPER THICKNESS:" at 10897.23,2055.64 h60
  text "X" at 12247.46,2055.64 h60
  text "1MIL" at 12384.46,2055.64 h60
  text "OTHER" at 12881.46,2055.64 h60
  text "BOARD FINISH:" at 10822.46,1896.64 h60
  text "SILKSCREEN:" at 10977.68,1778.64 h60
  text "X" at 11926.46,1778.64 h60
  text "TOP" at 12052.46,1778.64 h60
  text "X" at 12436.46,1778.64 h60
  text "BOTTOM" at 12563.46,1778.64 h60
  text "SILKSCREEN COLOR:" at 10977.68,1611.64 h60
  text "X" at 11925.42,1611.64 h60
  text "WHITE" at 12052.46,1611.64 h60
  text "OTHER" at 12563.46,1611.64 h60
  text "SOLDER RESIST COLOR:" at 10977.68,1441.64 h60
  text "GREEN" at 11672.46,1282.44 h60
  text "BLUE" at 12263.46,1282.44 h60
  text "OTHER" at 12801.46,1282.44 h60
  text "X" at 12650,1280 h60
  text "BLACK" at 13160,1270 h200
  text "IMMERSION GOLD (ENIG)" at 11883.46,1093.92 h60
  text "SURFACE FINISH:" at 10822.46,1089.64 h60
  text "X" at 11696.51,1089.64 h60
  text "IMM. TIN/SILVER OR EQUIV" at 11152,932.64 h60
  text "OTHER" at 12583.46,932.64 h60
  text "ARRAY/PANEL:" at 10822.46,753.64 h60
  text "CUT AND TRIM PER MECH LAYER 1" at 11883.46,749.35 h60
  text "N.C. ROUTE" at 11883.46,597.64 h60
  text "X" at 12562.46,597.64 h60
  text "V. SCORE" at 12749.46,597.64 h60
  text "CERTIFICATION:" at 10822.46,460.64 h60
  text "MATERIALS AND WORKMANSHIP FOR ALL PCBS" at 11547.46,460.64 h60
  text "TO MEET OR EXCEED THE REQUIREMENTS OF:" at 11547.46,362.64 h60
  text "X" at 11173.96,226.13 h60
  text "ANSI IPC-A-600F CLASS ->" at 11312.96,226.13 h60
  text "X" at 12952.02,226.13 h60
  text "2" at 13070.96,226.14 h60
  text "1" at 12755.96,224.64 h60
  text "3" at 13424.96,224.64 h60
  text "X" at 11176.02,66.64 h60
  text "UL 94V-0" at 11312.96,66.64 h60
  text "X" at 11988.02,66.64 h60
  text "RoHS" at 12124.96,66.64 h60
  text "OTHER" at 12769.36,66.64 h60
  text "PER ORDER" at 13166.42,66.64 h60
  text "ADDITIONAL REQUIREMENTS:" at 10822.46,-74.36 h60
  text "MICROSECTION:" at 10897.23,-189.36 h60
  text "YES" at 11802.96,-189.36 h60
  text "REQUIRED" at 12664.46,-345.51 h60
  text "BARE BOARD ELEC. TEST:" at 10897.23,-348.36 h60
  text "NONE" at 12202.96,-348.36 h60
  text "X" at 12537.46,-348.36 h60
  text "PER ORDER" at 13256.46,-348.36 h60
  text "MANUFACTURER'S ID/LOGO:" at 10897.23,-505.36 h60
  text "RAIL" at 12362.96,-509.65 h60
  text "X" at 12737.46,-509.65 h60
  text "METAL" at 12854.77,-509.65 h60
  text "SILK" at 13366.46,-509.65 h60
  text ".Layer_Name" at 67,-2318.49 h60
  text ".Layer_Name" at 67,-2318.49 h60
M11 Gerber Information:
  lines w10: -802,-2390.17 5798,-2390.17 ; -802,-2186.83 5800,-2186.83 ; -802,-1983.5 -802,-2593.5 3203,-2593.5 5800,-2593.5 5800,-1983.5 -801.5,-1983.5 -801.5,-2593.5 774,-2593.5 ; 1663,-2593.5 1663,-1983.5 ; 2930,-2186.83 2930,-1983.5 ; 3770,-2186.83 3770,-1983.5 ; 4392,-2600 4392,-2397.17
  text "ALL ARTWORK VIEWED FROM TOP SIDE" at -738.5,-2115.67 h60
  text "BOARD #:" at 1738,-2115.67 h60
  text ".PRJ_Number" at 2283.5,-2115.67 h60
  text "REV:" at 3128,-2115.67 h60
  text ".PCB_Rev" at 3419.5,-2115.67 h60
  text "SVN REV:" at 3966,-2115.67 h60
  text ".VersionControl_RevNumber" at 4472,-2115.67 h60
  text "LAYER NAME =" at -738.5,-2318.49 h60
  text "PLOT NAME =" at -738.5,-2524.34 h60
  text ".plot_File_Name" at 67,-2524.34 h60
  text "GENERATED    :" at 1740,-2524.34 h60
  text ".Print_Date" at 2609.5,-2524.34 h60
  text ".Print_Time" at 3338.5,-2524.34 h60
  text "TEXAS INSTRUMENTS" at 4603,-2524.34 h60
M12 Stackup:
  drawing of 191 lines, arcs and shapes, not listed
  text "Layer" at 6142.5,6332.5 h60
  text "Name" at 6552.41,6332.5 h60
  text "Material" at 7482.16,6332.5 h60
  text "Thickness" at 8341.92,6332.5 h60
  text "Constant" at 8991.76,6332.5 h60
  text "Board Layer Stack" at 9561.62,6332.5 h60
  text "1" at 6142.5,6212.5 h60
  text "Top Overlay" at 6552.41,6212.5 h60
  text "2" at 6142.5,6092.5 h60
  text "Top Solder" at 6552.41,6092.5 h60
  text "Solder Resist" at 7482.16,6092.5 h60
  text "0.40mil" at 8341.92,6092.5 h60
  text "3.5" at 8991.76,6092.5 h60
  text "3" at 6142.5,5972.5 h60
  text "Top Layer" at 6552.41,5972.5 h60
  text "Copper" at 7482.16,5972.5 h60
  text "1.40mil" at 8341.92,5972.5 h60
  text "4" at 6142.5,5852.5 h60
  text "Dielectric1" at 6552.41,5852.5 h60
  text "FR-4" at 7482.16,5852.5 h60
  text "59.20mil" at 8341.92,5852.5 h60
  text "4.8" at 8991.76,5852.5 h60
  text "5" at 6142.5,5732.5 h60
  text "Bottom Layer" at 6552.41,5732.5 h60
  text "Copper" at 7482.16,5732.5 h60
  text "1.40mil" at 8341.92,5732.5 h60
  text "6" at 6142.5,5612.5 h60
  text "Bottom Solder" at 6552.41,5612.5 h60
  text "Solder Resist" at 7482.16,5612.5 h60
  text "0.40mil" at 8341.92,5612.5 h60
  text "3.5" at 8991.76,5612.5 h60
  text "7" at 6142.5,5492.5 h60
  text "Bottom Overlay" at 6552.41,5492.5 h60
  text ".Layer_Name" at 67,-2318.49 h60
M13 Component Bodies Top:
  text ".Layer_Name" at 67,-2318.49 h60
M14 Component Bodies Bottom:
  text ".Layer_Name" at 67,-2318.49 h60
M15 Courtyards Top:
  text ".Layer_Name" at 67,-2318.49 h60
M16 Courtyards Bottom:
  text ".Layer_Name" at 67,-2318.49 h60
Drill Drawing:
  circle w10: c6143.65,4883.03 r27.6
  lines w10: 6116.05,4993.44 6129.85,4993.44 6129.85,4979.64 6157.45,4979.64 6157.45,4993.44 6171.25,4993.44 6171.25,5021.04 6157.45,5021.04 6157.45,5034.84 6129.85,5034.84 6129.85,5021.04 6116.05,5021.04 6116.05,4993.44 ; 6116.05,5103.84 6171.25,5103.84 6171.25,5159.05 6116.05,5159.05 6116.05,5103.84
  lines w12: 6066,4818.16 9295.78,4818.16 ; 6066,5190.79 9295.78,5190.79 ; 6403.73,4693.95 6403.73,5315 ; 6735.48,4693.95 6735.48,5315 ; 7371.79,4693.95 7371.79,5315 ; 7630.78,4693.95 7630.78,5315 ; 8005.81,4693.95 8005.81,5315 ; 8729.56,4693.95 8729.56,5315 ; 6066,4693.95 9295.78,4693.95 9295.78,5315 6066,5315 6066,4693.95
  text "Symbol" at 6140.53,5228.05 h72
  text "Quantity" at 6440.99,5228.05 h72
  text "Finished Hole Size" at 6772.74,5228.05 h72
  text "Plated" at 7409.05,5228.05 h72
  text "Hole Type" at 7668.04,5228.05 h72
  text "Drill Layer Pair" at 8043.08,5228.05 h72
  text "Hole Tolerance" at 8766.82,5228.05 h72
  text "2" at 6440.99,5103.84 h60
  text "110.24mil (2.800mm)" at 6772.74,5103.84 h60
  text "NPTH" at 7409.05,5103.84 h60
  text "Round" at 7668.04,5103.84 h60
  text "Top Layer - Bottom Layer" at 8043.08,5103.84 h60
  text "+3.94mil" at 8766.82,5103.84 h60
  text "27" at 6440.99,4979.64 h60
  text "20.00mil (0.508mm)" at 6772.74,4979.64 h60
  text "PTH" at 7409.05,4979.64 h60
  text "Round" at 7668.04,4979.64 h60
  text "Top Layer - Bottom Layer" at 8043.08,4979.64 h60
  text "48" at 6440.99,4855.43 h60
  text "39.37mil (1.000mm)" at 6772.74,4855.43 h60
  text "PTH" at 7409.05,4855.43 h60
  text "Round" at 7668.04,4855.43 h60
  text "Top Layer - Bottom Layer" at 8043.08,4855.43 h60
  text "+/-3.94mil" at 8766.82,4855.43 h60
  text "77 Total" at 6440.99,4731.22 h60
  text ".Layer_Name" at 67,-2318.49 h60
Mechanical 18:
  circle w10: c1400,1900 r380
  circle w10: c1400,1900 r805
  circle w10: c3700,1500 r200
  circle w10: c5100,2300 r200
  circle w10: c5100,1500 r200
  circle w10: c3000,1500 r200
  circle w10: c4400,1500 r200
  circle w10: c4400,2300 r200
  circle w10: c3700,2300 r200
  circle w10: c3000,2300 r200
  lines w1: 0,0 6000,0 6000,3500 4110,3500 ccw(c4110,3480) 4090,3480 4090,3270 cw(c4070,3270) 4070,3250 3840,3250 ccw(c3840,3210) 3800,3210 3800,3060 cw(c3780,3060) 3780,3040 2200,3040 cw(c2200,3060) 2180,3060 2180,3210 ccw(c2140,3210) 2140,3250 1930,3250 cw(c1930,3270) 1910,3270 1910,3480 ccw(c1890,3480) 1890,3500 0,3500 0,0
  lines w9.84: 175,250 5815,250 5815,700 175,700 175,250

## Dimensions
6000,0 to 6000,3500 on M2 Board Dimensions
0,3500 to 6000,3500 on M2 Board Dimensions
